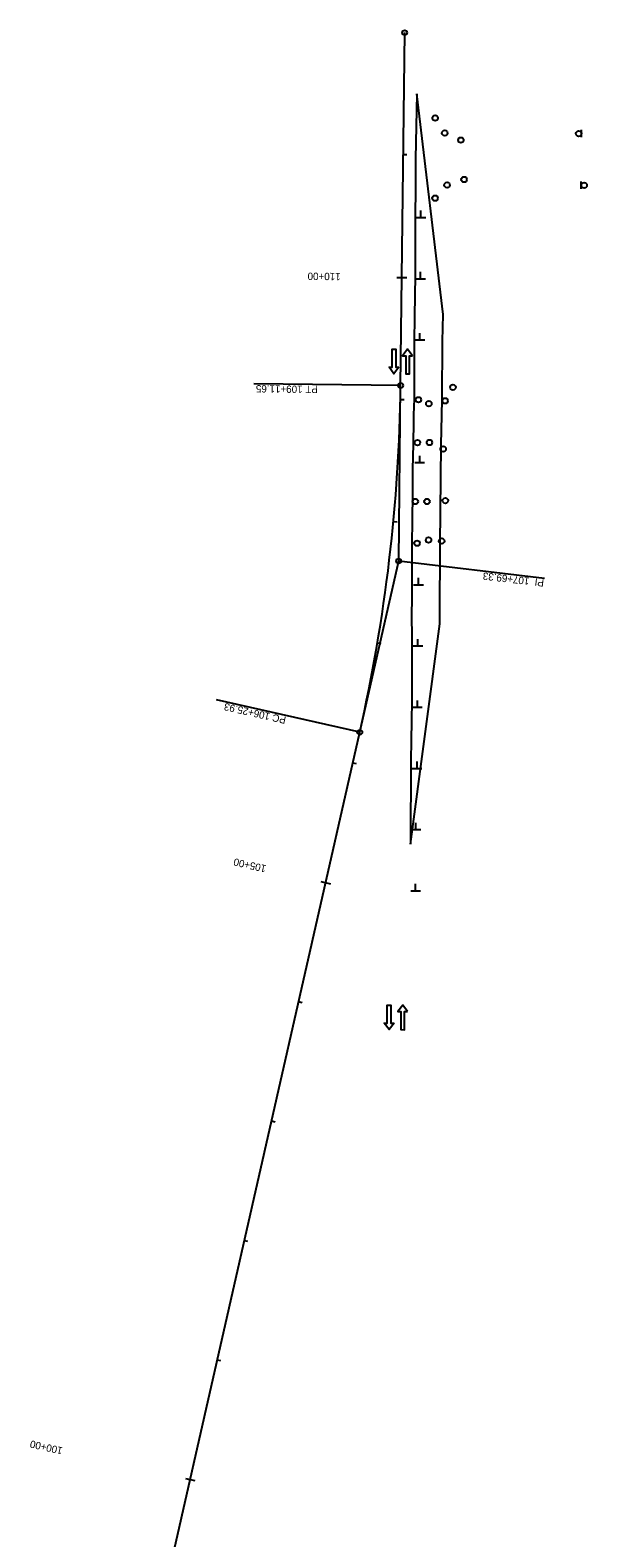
# Model space of a CAD drawing. Extents: x 1710760 to 1712674, y 548603 to 551099.
# Drawn here: x 1712182 to 1712636, y 549868 to 551099 of the extents above; entities that cross this region are included whole.
import ezdxf

# ---------------------------------------------------------------- set-up
doc = ezdxf.new("R2010")
doc.units = 0
for name, color, linetype in [('R_Horz Alg', 7, 'Continuous'), ('R_Horz Alg Annot', 7, 'Continuous'), ('R_MOT', 7, 'Continuous')]:
    doc.layers.add(name, color=color, linetype=linetype)

msp = doc.modelspace()

# ---------------------------------------------------------------- linework, layer by layer
at = {"layer": 'R_Horz Alg'}
for p, q in [((1712484.2, 550809.1), (1712487.5, 551097.3)), ((1712246.8, 549627.3), (1712450.8, 550525.8))]:
    msp.add_line(p, q, dxfattribs=at)
msp.add_arc((1711136.1, 550824.3), 1348.1, 347.2066, 359.3498, dxfattribs=at)
at = {"layer": 'R_Horz Alg Annot'}
for p, q in [((1712482.6, 550665.7), (1712484.2, 550809.1)), ((1712450.8, 550525.8), (1712482.6, 550665.7))]:
    msp.add_line(p, q, dxfattribs=at)
for points in [[(1712489.3, 550997.4), (1712486.3, 550997.4)], [(1712481.2, 550897.4), (1712489.2, 550897.3)], [(1712484.2, 550809.1), (1712364.2, 550810.4)], [(1712487, 550797.3), (1712484, 550797.4)], [(1712481.3, 550697.3), (1712478.3, 550697.6)], [(1712482.6, 550665.7), (1712601.7, 550651.6)], [(1712468.2, 550598), (1712465.2, 550598.5)], [(1712450.8, 550525.8), (1712333.8, 550552.4)], [(1712448, 550499.9), (1712445.1, 550500.5)], [(1712419, 550403.9), (1712426.8, 550402.1)], [(1712403.7, 550304.8), (1712400.8, 550305.5)], [(1712381.6, 550207.3), (1712378.6, 550208)], [(1712359.4, 550109.8), (1712356.5, 550110.5)], [(1712337.3, 550012.3), (1712334.3, 550013)], [(1712308.3, 549916.3), (1712316.1, 549914.5)]]:
    msp.add_lwpolyline(points, dxfattribs=at)
for centre in [(1712487.5, 551097.3), (1712484.2, 550809.1), (1712482.6, 550665.7), (1712450.8, 550525.8)]:
    msp.add_circle(centre, 2, dxfattribs=at)
at = {"layer": 'R_MOT'}
for p, q in [((1712518.8, 550867), (1712497.3, 551047.3)), ((1712631.8, 551017.8), (1712631.8, 551011.8)), ((1712631.8, 550969.6), (1712631.8, 550975.6)), ((1712500.7, 550946.4), (1712500.7, 550951.9)), ((1712496.7, 550946.3), (1712504.7, 550946.3)), ((1712500.5, 550896.4), (1712500.5, 550901.9)), ((1712496.6, 550896.3), (1712504.6, 550896.3)), ((1712499.9, 550846.4), (1712499.9, 550851.9)), ((1712495.9, 550846.3), (1712503.9, 550846.3)), ((1712499.8, 550746.3), (1712499.8, 550751.7)), ((1712495.8, 550746.2), (1712503.8, 550746.2)), ((1712498.8, 550646.4), (1712498.8, 550651.9)), ((1712494.8, 550646.3), (1712502.8, 550646.3)), ((1712492.1, 550434.5), (1712516.1, 550614.5)), ((1712494.3, 550596.3), (1712502.3, 550596.4)), ((1712498.3, 550596.4), (1712498.2, 550601.9)), ((1712493.9, 550546.3), (1712501.9, 550546.2)), ((1712497.9, 550546.4), (1712497.9, 550551.8)), ((1712493.6, 550496.3), (1712501.6, 550496.2)), ((1712497.6, 550496.3), (1712497.6, 550501.8)), ((1712492.7, 550446.3), (1712500.7, 550446.3)), ((1712496.7, 550446.4), (1712496.7, 550451.9)), ((1712492.4, 550396.3), (1712500.4, 550396.3)), ((1712496.4, 550396.4), (1712496.4, 550401.9))]:
    msp.add_line(p, q, dxfattribs=at)
for points in [[(1712497.3, 551047.3), (1712496.4, 550994.1), (1712496.3, 550970.5), (1712496.1, 550946.9), (1712496.1, 550929.6), (1712496, 550912.4), (1712496, 550897.9), (1712495.9, 550883.5), (1712495.6, 550864.5), (1712495.3, 550845.5), (1712495.2, 550821.9), (1712495.1, 550798.3), (1712494.7, 550785.1), (1712494.6, 550779.9), (1712494.3, 550761.1), (1712494, 550740.6), (1712493.8, 550720.1), (1712493.6, 550699.6), (1712493.4, 550679), (1712493.3, 550664.5), (1712493.2, 550650), (1712493.2, 550635.6), (1712493.1, 550621.1), (1712493.2, 550603.6), (1712493.2, 550586.2), (1712493.3, 550568.8), (1712493.4, 550551.4), (1712493.1, 550535.2), (1712492.8, 550519), (1712492.6, 550502.7), (1712492.1, 550434.5)], [(1712516.1, 550614.5), (1712516.1, 550621), (1712516.4, 550678.9), (1712517.3, 550760.8), (1712517.7, 550784.5), (1712518.1, 550797.8), (1712518.3, 550845.3), (1712518.8, 550867)]]:
    msp.add_lwpolyline(points, dxfattribs=at)
for points in [[(1712482.7, 550823.9), (1712478.7, 550818.7), (1712474.7, 550823.9), (1712477.2, 550823.9), (1712477.3, 550838.6), (1712480.3, 550838.6), (1712480.2, 550823.9)], [(1712493.8, 550833.4), (1712489.8, 550838.6), (1712485.8, 550833.4), (1712488.3, 550833.4), (1712488.3, 550818.7), (1712491.3, 550818.7), (1712491.3, 550833.4)], [(1712478.8, 550288.1), (1712474.8, 550282.9), (1712470.8, 550288.1), (1712473.3, 550288.1), (1712473.3, 550302.8), (1712476.3, 550302.8), (1712476.3, 550288.1)], [(1712489.9, 550297.6), (1712485.9, 550302.8), (1712481.9, 550297.6), (1712484.4, 550297.6), (1712484.3, 550282.9), (1712487.3, 550282.8), (1712487.4, 550297.6)]]:
    msp.add_lwpolyline(points, close=True, dxfattribs=at)
for centre in [(1712512.4, 551027.5), (1712520.2, 551015.3), (1712533.4, 551009.5), (1712629.6, 551014.8), (1712522.1, 550972.8), (1712536, 550977.3), (1712634.1, 550972.6), (1712512.3, 550962.1), (1712498.7, 550797.4), (1712526.9, 550807.6), (1712507.2, 550794.2), (1712520.5, 550796.5), (1712497.9, 550762.4), (1712507.7, 550762.5), (1712518.9, 550757.2), (1712496.2, 550714.3), (1712505.7, 550714.3), (1712520.7, 550715), (1712497.6, 550680.2), (1712507, 550682.8), (1712517.7, 550682)]:
    msp.add_circle(centre, 2.25, dxfattribs=at)

# ---------------------------------------------------------------- texts
at = {"layer": 'R_Horz Alg Annot'}
for s, rotation, p in [('110+00', 179.3498, (1712435.2, 550901)), ('PT 109+11.65', 179.3498, (1712416.6, 550808.8)), ('PI  107+69.33', 173.2782, (1712601.6, 550650.6)), ('PC 106+25.93', 167.2066, (1712391, 550538.4)), ('105+00', 167.2066, (1712374.8, 550417)), ('100+00', 167.2066, (1712208.5, 549941.5))]:
    msp.add_text(s, height=6, rotation=rotation, dxfattribs=at).set_placement(p)

doc.saveas('drawing.dxf')
